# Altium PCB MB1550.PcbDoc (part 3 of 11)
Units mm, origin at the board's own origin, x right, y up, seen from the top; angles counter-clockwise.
Board outline 154.81 x 170.69 mm, 6 copper layers (Top Layer, Signal Layer 1, Signal Layer 2, Signal Layer 3, Signal Layer 4, Bottom Layer), stack 1.49 mm thick; 810 components, 633 nets, 2973 pads, 2150 vias.
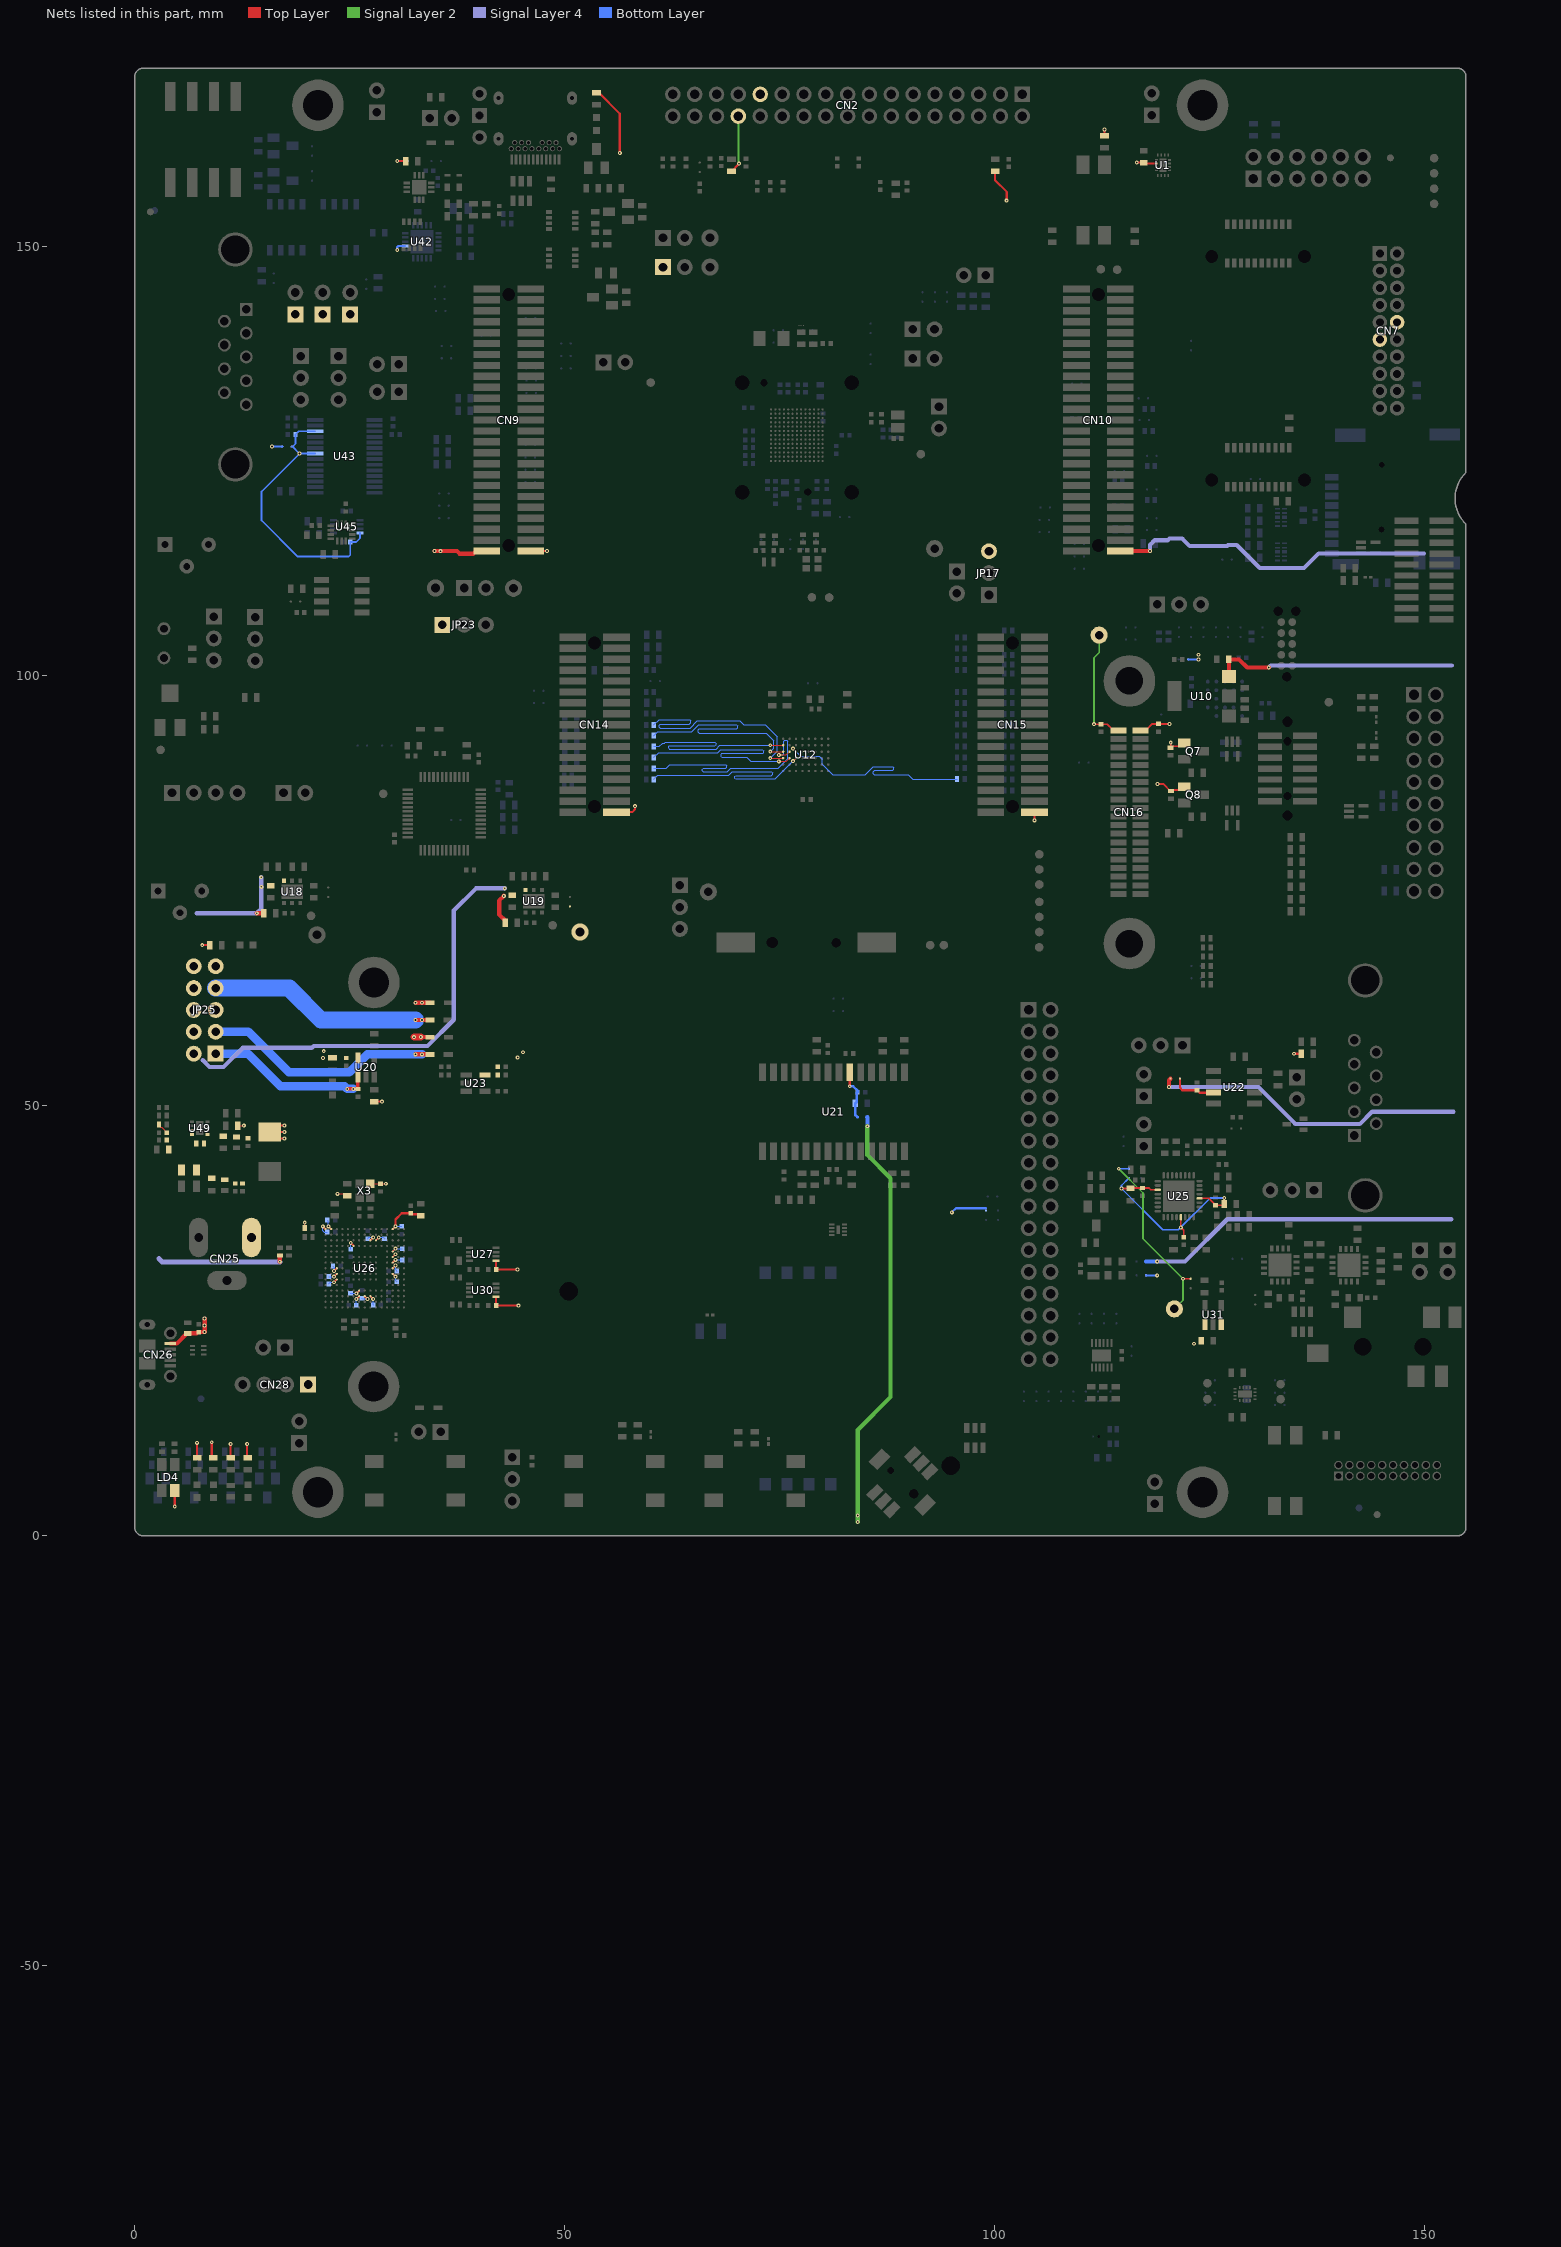
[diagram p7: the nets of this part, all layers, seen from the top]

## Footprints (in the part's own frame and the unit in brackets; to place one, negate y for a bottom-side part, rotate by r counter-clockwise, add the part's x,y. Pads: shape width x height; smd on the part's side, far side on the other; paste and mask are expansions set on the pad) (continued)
PowerFLAT_5x6 [mm] "MCD-02152"
  rect 0.65x1.25 smd mask+0.05: 1(1.905,2.675) 2(0.635,2.675) 3(-0.635,2.675) 4(-1.905,2.675) 5(-1.905,-2.675) 6(-0.635,-2.675) 7(0.635,-2.675) 8(1.905,-2.675)
  Top Layer region: -0.2,-3.3 -0.95,-3.3 -0.95,-2.75 -1.575,-2.75 -1.575,-3.3 -2.3,-3.3 -2.3,-2.3 -2.7,-2.3 -2.7,-1.5 -2.3,-1.5 -2.3,0.15 -2.7,0.15 -2.7,0.975 -2.3,0.975 -2.3,1.15 -0.2,1.15
  Top Layer region: 0.2,-3.3 0.95,-3.3 0.95,-2.75 1.575,-2.75 1.575,-3.3 2.3,-3.3 2.3,-2.3 2.7,-2.3 2.7,-1.5 2.3,-1.5 2.3,0.15 2.7,0.15 2.7,0.975 2.3,0.975 2.3,1.15 0.2,1.15
  silkscreen extent -2.5,-3 2.5,3, body extent -2.6,-3.08 2.6,3.07, height 1
PTC_Panasonic_micro_chip_fuse_0402 [mm] "MCD-02197"
  rect 0.51x0.7 smd mask+0.05: 1(-0.45,0) 2(0.45,0)
  silkscreen extent 0,-0.3 0,0.3, body extent -0.52,-0.3 0.52,0.3, height 0.4
PTH_M1261-3005-N_3P5X6_M3_H14 [mm]
  round 6 hole 3.5 mask+0.05: 1(0,0)
  silkscreen extent -3.25,-3.25 3.25,3.25, body extent -2.5,-2.5 2.5,2.5, height 14
R0402 [mm]
  rect 0.51x0.7 smd mask+0.05: 1(-0.45,0) 2(0.45,0)
  silkscreen extent 0,-0.3 0,0.3, body extent -0.52,-0.3 0.52,0.3, height 0.4
R0603 [mm]
  rect 0.64x1 smd mask+0.05: 1(-0.7,0) 2(0.7,0)
  silkscreen extent -1.05,-0.58 1.05,0.58, body extent -0.9,-0.5 0.9,0.5, height 0.56
R0603_H0P45 [mm]
  rect 0.64x1 smd mask+0.05: 1(-0.7,0) 2(0.7,0)
  silkscreen extent -1.05,-0.58 1.05,0.58, body extent -0.9,-0.5 0.9,0.5, height 0.56
R0805 [mm]
  rect 0.85x1.3 smd mask+0.05: 1(-0.875,0) 2(0.875,0)
  silkscreen extent -0.33,-0.67 0.33,0.67, body extent -1.05,-0.68 1.05,0.68, height 0.65
R0805_H0P5 [mm] "MCD-01537"
  rect 0.85x1.3 smd mask+0.05: 1(-0.875,0) 2(0.875,0)
  silkscreen extent -0.33,-0.67 0.33,0.67, body extent -1.05,-0.68 1.05,0.68, height 0.6
REG_SOT23-5L [mm]
  rect 0.6x1.3 smd mask+0.05: 1(-0.95,-1.1) 2(0,-1.1) 3(0.95,-1.1) 4(0.95,1.1) 5(-0.95,1.1)
  silkscreen extent -1.6,-0.95 1.6,0.97, body extent -1.52,-1.25 1.52,1.25, height 1.1
REG_SOT223-TAB [mm]
  rect 1.5x1.65 smd mask+0.05: 1(-2.3,-3.175) 2(0,-3.175) 3(2.3,-3.175)
  rect 3.5x1.65 smd mask+0.05: 4(0,3.175)
  silkscreen extent -3.35,-2.15 3.35,2.12, body extent -3.35,-3.48 3.35,3.48, height 1.8
SOLDER-BRIDGE_R0603-0R [mil]
  round 10 smd paste-393.7: 1(-19.68,0) 2(23.62,0)
  Top Layer region: -47.24,-19.68 -47.24,19.68 -15.75,19.68 3.94,0 -15.75,-19.68 -47.24,-19.68
  Top Layer region: -5.91,19.68 13.78,0 -5.91,-19.68 47.24,-19.68 47.24,19.68 -5.91,19.68
  silkscreen extent -50,-23 50,23, body extent -36,-20 36,20, height 22
STICKER_BOARD_25X9 [mm] "Sticker to mention board CPN code"
  silkscreen extent -12.5,-4.5 12.5,4.5
STICKER_PRODUCT_25X9 [mm] "Sticker to mention board CPN code"
  silkscreen extent -12.5,-4.5 12.5,4.5
SWI_C&K_SDA02H1SBD_2POS [mm]
  rect 1.5x2.15 smd mask+0.05: 1(-1.27,-4.125) 2(1.27,-4.125) 3(1.27,4.125) 4(-1.27,4.125)
  silkscreen extent -3.55,-3.75 3.55,3.75, body extent -3.53,-4.65 3.53,4.65, height 5.45
SWI_EAO_09-03290-01_EXTENDED_STRAIGHT_BLACK [mm]
  rect 1.7x1.7 hole 0.9 mask+0.05: 1(0,0)
  round 1.7 hole 0.9 mask+0.05: 2(0,-2.54) 3(0,2.54)
  silkscreen extent -1.25,-5 1.25,5, body extent -1.25,-5 1.25,5, height 7.9
SWI_WEALTHMETAL_TD-0341_4P_BLACK [mm]
  rect 1.52x2.16 smd mask+0.05: 1(-2.25,-4.75) 2(-2.25,4.75) 3(2.25,-4.75) 4(2.25,4.75)
  silkscreen extent -3,-3.5 3,3.5, body extent -3,-5.15 3,5.15, height 7.55
SWI_WEALTHMETAL_TD-0341_4P_BLUE [mm]
  rect 1.52x2.16 smd mask+0.05: 1(-2.25,-4.75) 2(-2.25,4.75) 3(2.25,-4.75) 4(2.25,4.75)
  silkscreen extent -3,-3.5 3,3.5, body extent -3,-5.15 3,5.15, height 7.55
SWI_XIEJIA_MT-008A_6P [mm] "MCD-00132"
  rect 1.8x1.1 smd mask+0.05: 1(-3.1,1.4) 2(-3.1,0) 3(-3.1,-1.4) 4(3.1,1.4) 5(3.1,0) 6(3.1,-1.4)
  rect 2.2x1.4 smd mask+0.05: 7(0,3.75) 8(0,-3.75)
  round 0 hole 0.8 unplated paste-10 mask+0.05: NPTH1(0,1.9)
  round 0 hole 1.1 unplated paste-10 mask+0.05: NPTH2(0,-1.9)
  silkscreen extent -3.7,-3.7 3.7,3.7, body extent -3.85,-3.75 3.85,3.75, height 5.2
TP_PTH_1MM_2MM [mm] "MCD-01506"
  round 2 hole 1 mask+0.05: 1(0,0)
  silkscreen extent -1.2,-1.2 1.2,1.2
TP_SMD_1MM [mm]
  round 1 smd paste-10 mask+0.05: 1(0,0)
  silkscreen extent -0.7,-0.7 0.7,0.7
TSB_TOUCH-SENSING-BUTTON_TS-PAD-10_SHIELD-14 [mm]
  round 0.1 smd paste-10 mask+0.05: SHIELD(-0.26,-7.25) SHIELD(0.26,-7.25)
  round 0.12 smd paste-10 mask+0.05: TKEY(0,-7.25)
  Top Layer region: 0,5 -1.913,4.619 -3.536,3.536 -4.619,1.913 -5,0 -5,0 0,0 -5,0 -4.619,-1.913 -3.536,-3.536 -1.913,-4.619 0,-5 0,-5 1.913,-4.619 3.536,-3.536 4.619,-1.913 5,0 5,0 4.619,1.913 3.536,3.536 1.913,4.619 0,5 0,5 0,0
  Top Layer region: -0.21,-5.146 -2.695,-4.388 -4.495,-2.514 -5.15,0 -5.15,0 -4.758,1.971 -3.642,3.642 -1.971,4.758 0,5.15 0,5.15 0,7 -7,7 -7,-7 -0.21,-7
  Top Layer region: 0,5.15 1.971,4.758 3.642,3.642 4.758,1.971 5.15,0 5.15,0 4.495,-2.514 2.695,-4.388 0.21,-5.146 0.21,-5.146 0.21,-7 7,-7 7,7 0,7
  Top Layer lines w0.1: -0.26,-7.25 -0.26,-5.25 ; 0.26,-7.25 0.26,-5.25
  Top Layer lines w0.12: 0,-7.25 0,0
  silkscreen extent -7.12,-7.12 7.12,7.12, body extent -7,-7 7,7, height 4

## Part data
B1: library part MCD-00132, "Joystick, 4 dir, 1 OK", Manufacturer="XIEJIA Electronics", Manufacturer_Part_Number=MT-008A
B2: library part MCD-00001, "Non-Open Push-Button 0.1A 24V", Manufacturer=WEALTHMETAL, Manufacturer_Part_Number=TD0341X-G01-BLA
B3 B4: library part MCD-00002, "Non-Open Push-Button 0.1A 24V", Manufacturer=WEALTHMETAL, Manufacturer_Part_Number=TD0341X-G01-BLU
C1 C33 C39 C66 C72 C76 C77 C80 C85 C87 C88 C89 C96 C99 C100 C101 C102 C109 C145 C148 C149 C180 C181 C188: library part MCD-00010, "Capacitor, MLCC, 1uF, 16V, X5R, 10%, 0603, T=0,8mm", Manufacturer=YAGEO, Manufacturer_Part_Number=CC0603KRX5R7BB105, Package=C0603
C2 C10: library part MCD-00198, "Capacitor, MLCC, 1nF, 16V, X7R, 10%, 0402, T=0.5mm", Manufacturer=YAGEO, Manufacturer_Part_Number=CC0402KRX7R7BB102, Package=C0402
C3 C4 C5 C6 C7 C8 C9 C11 C12 C13 C14 C15 C25 C26 C32 C36 C37 C38 C40 C41 C42 C43 C44 C45 C50 C51 C52 C53 C56 C57 C59 C63 C64 C68 C70 C71 C74 C75 C78 C79 C83 C90 C93 C94 C95 C98 C103 C104 C105 C110 C111 C119 C120 C121 C122 C123 C124 C125 C126 C127 C129 C131 C132 C133 C134 C135 C136 C139 C140 C141 C142 C143 C146 C147 C151 C152 C153 C154 C155 C156 C158 C159 C161 C162 C163 C164 C165 C166 C167 C168 C169 C170 C172 C173 C174 C175 C176 C178 C179: library part MCD-00006, "Capacitor, MLCC, 100nF, 16V, X7R, 10%, 0402, T=0.5mm", Alternate_Manufacturer=MURATA, Alternate_Manufacturer_Part_Number=GCM155R71C104KA55D, Manufacturer=YAGEO, Manufacturer_Part_Number=CC0402KRX7R7BB104, Package=C0402
C16 C62 C97: library part MCD-00011, "Capacitor, MLCC, 10nF, 16V, X7R, 10%, 0402, T=0.5mm", Manufacturer=YAGEO, Manufacturer_Part_Number=CC0402KRX7R7BB103, Package=C0402
C17 C116: library part MCD-01099, "Capacitor,100nF,50V,X7R,10%,0603", Manufacturer=YAGEO, Manufacturer_Part_Number=CC0603KRX7R9BB104, Package=C0603
C18: library part MCD-00015, "Capacitor, MLCC, 10pF, 50V, NPO, 5%, 0402, T=0,5mm", Manufacturer=YAGEO, Manufacturer_Part_Number=CC0402JRNPO9BN100, Package=C0402
C19 C114 C115 C117: library part MCD-00211, "Capacitor, MLCC, 100nF, 16V, X7R, 10%, 0603, T=0,8mm", Manufacturer=YAGEO, Manufacturer_Part_Number=CC0603KRX7R7BB104, Package=C0603
C20: library part MCD-01939, "Capacitor, COG, 39nF,50V, 5%, 1206, T=0.85mm", Manufacturer=MURATA, Manufacturer_Part_Number=GRM3195C1H393JA01D, Package=C1206
C21: library part MCD-02154, "Capacitor, MLCC, 390nF, 10V, X5R, 10%, 0402, T=0,5mm", Alternate_Manufacturer=N\A, Manufacturer=MURATA, Manufacturer_Part_Number=GMD155R61A394KE11J, Package=C0402
C22 C23 C137 C138 C171 C177: library part MCD-01823, "Capacitor,MLCC,2.2uF,6V3,X5R,10%,0402,T=0.5", Manufacturer=MURATA, Manufacturer_Part_Number=GRM155R60J225KE95D, Package=C0402
C24 C107: library part MCD-00205, "Capacitor, MLCC, 100pF, 50V, NPO, 5%, 0402, T=0,5mm", Manufacturer=YAGEO, Manufacturer_Part_Number=CC0402JRNPO9BN101, Package=C0402
C27 C35 C46 C47 C48 C49 C73 C81 C91 C118 C157 C160: library part MCD-00009, "Capacitor, MLCC, 4.7uF, 16V, X5R, 10%, 0603, T=0.8mm", Manufacturer=YAGEO, Manufacturer_Part_Number=CC0603KRX5R7BB475, Package=C0603
C28 C29 C30 C31: library part MCD-00556, "Capacitor, MLCC, 3.9pF, 50V, NPO, +-0.25pF, 0402, T=0,5mm", Manufacturer=YAGEO, Manufacturer_Part_Number=CC0402CRNPO9BN3R9, Package=C0402
C34 C69 C128 C130 C144: library part MCD-01355, "Capacitor, MLCC, 10uF, 4V, X5R, 20%, 0402, T=0,5mm", Manufacturer=MURATA, Manufacturer_Part_Number=GRM155R60G106ME44, Package=C0402
C54 C55 C58 C61 C82: library part MCD-00095, "Capacitor, MLCC, 1uF, 25V, X5R, 10%, 0402, T=0,5mm", Alternate_Manufacturer=MURATA, Alternate_Manufacturer_Part_Number=GRM155R60J105KE19, Manufacturer_Part_Number=GRM155R61E105KA12, Package=C0402
C60: library part MCD-00142, "Capacitor, Tantalum, 220uF, 10V, 10%, TypeC", Manufacturer=AVX, Manufacturer_Part_Number=TAJC227K010R, Package=C2312
C65 C67: library part MCD-00304, "Capacitor, MLCC, 150pF, 50V, COG, 5%, 0603, T=0,8mm", Manufacturer=YAGEO, Manufacturer_Part_Number=CC0603JRNPO9BN151, Package=C0603
C84 C86: library part MCD-00555, "Capacitor, MLCC, 22nF, 10%, 25V, X7R, 0603, T=0,8mm", Manufacturer=YAGEO, Manufacturer_Part_Number=CC0603KRX7R8BB223, Package=C0603
C92: library part MCD-00014, "Capacitor, MLCC, 10uF, 25V, X5R, 10%, 0805, T=0,85mm", Manufacturer=YAGEO, Manufacturer_Part_Number=CC0805KRX5R8BB106, Package=C0805
C106: library part MCD-00012, "Capacitor, MLCC, 2.2uF, 10V, X5R, 10%, 0603, T=0,8mm", Alternate_Manufacturer=KEMET, Alternate_Manufacturer_Part_Number=C0603C225K8PACTU, Manufacturer=YAGEO, Manufacturer_Part_Number=CC0603KRX5R6BB225, Package=C0603
C108: library part MCD-00016, "Capacitor, MLCC, 20pF, 50V, NPO, 5%, 0402, T=0,5mm", Manufacturer=YAGEO, Manufacturer_Part_Number=CC0402JRNPO9BN200, Package=C0402
C112 C113: library part MCD-01579, "Capacitor, MLCC, 330pF, 50V, NPO, +/-5%, 0402, T=0,5mm", Manufacturer=YAGEO, Manufacturer_Part_Number=CC0402JRNPO9BN331, Package=C0402
C150: library part MCD-00100, "Capacitor, MLCC, 22uF, 6V3, X5R, 20%, 0603, T=0,8mm", Manufacturer=MURATA, Manufacturer_Part_Number=GRM188R60J226MEA0J, Package=C0603
C182 C187: library part MCD-00015, "Capacitor, MLCC, 10pF, 50V, NPO, +/-5%, 0402, T=0,5mm", Manufacturer=YAGEO, Manufacturer_Part_Number=CC0402JRNPO9BN100, Package=C0402
C183 C186: library part MCD-02198, "Capacitor, MLCC, 10nF, 50V ,X7R, +/-10%, 0402, T=0.5mm", Alternate_Manufacturer="TAIYO YUDEN", Alternate_Manufacturer_Part_Number=UMF105B7103KVHF, Manufacturer=YAGEO, Manufacturer_Part_Number=CC0402KRX7R9BB103, Package=C0402
C184 C185: library part MCD-02196, "Capacitor, MLCC, 4.7uF, 25V, X5R, +/-10%, 0603, T=0,8mm", Alternate_Manufacturer="TAIYO YUDEN", Alternate_Manufacturer_Part_Number=TMK107BBJ475KA-T, Manufacturer=TDK, Manufacturer_Part_Number=C1608X5R1E475K080AC, Package=C0603
C189: library part MCD-00011, "Capacitor, MLCC, 10nF, 16V, X7R, +/-10%, 0402, T=0.5mm", Manufacturer=YAGEO, Manufacturer_Part_Number=CC0402KRX7R7BB103, Package=C0402
CN1: library part MCD-01108, "USB tyce C certified receptacle for 1.6mm pcb height", Manufacturer="CHANT SINCERE (COXOC)", Manufacturer_Part_Number=317JD24BZTF3K3C3
CN2: library part MCD-00583, "Header, 17x2, 2.54mm, VR, TH, Height 8.89mm/2.92mm, shrouded", Alternate_Manufacturer=WINPIN, Alternate_Manufacturer_Part_Number=BHFS03-34G01BT1, Manufacturer=SAMTEC, Manufacturer_Part_Number=TST-117-01-T-D
CN3: library part MCD-00308, "Socket, 6x2, 2.54mm, TH, RA, Height 8.51mm/7.62mm", Manufacturer=SAMTEC, Manufacturer_Part_Number=SSW-106-02-F-D-RA
CN4: library part MCD-00131, "Socket, 4x2, 2.54mm, RA, SMT, Height 5.72mm", Manufacturer=SAMTEC, Manufacturer_Part_Number=SSM-104-L-DH
CN5 CN11: library part MCD-00675, "Socket High Speed, 10x2, 0.8mm, Center Strip Contacts, VR, SMT, Height 5.33 mm", Manufacturer=SAMTEC, Manufacturer_Part_Number=ERF8-010-05.0-S-DV-TR, Package=ERF8
CN6 CN22: library part MCD-01978, "DB9_Male, RA, TH, height 13.575mm/3.8mm", Manufacturer=TYCO, Manufacturer_Part_Number=2301843-2, Package=TH
CN7: library part MCD-00309, "Socket 10x2, 2.00mm, RA, TH, Height 6.35mm/2.29mm", Alternate_Manufacturer=JIUBABA;CONNECT, Alternate_Manufacturer_Part_Number=FH200020C-12300;CNT-F200-2*10-GD-635/2.3, Manufacturer=SAMTEC, Manufacturer_Part_Number=SQT-110-01-F-D-RA
CN8 CN20: library part MCD-00032, "Header, 2x1, 2,54mm, VR, TH, Height 5.84mm/2.54mm", Manufacturer=SAMTEC, Manufacturer_Part_Number=TSW-102-07-x-S
CN9 CN10: library part MCD-02111, "Header 25x2, 1.27mm, VR, CMS, Height 7.24mm", Alternate_Manufacturer=N/A, Manufacturer=SAMTEC, Manufacturer_Part_Number=FTR-125-03-L-D-LC
CN12: library part MCD-00557, "Header 10x2, 1.27mm, VR, CMS, Height 3.05mm", Alternate_Manufacturer=JIUBABA, Alternate_Manufacturer_Part_Number=P127B-2*10MGF-079-1E7A, Manufacturer=SAMTEC, Manufacturer_Part_Number=FTSH-110-01-L-DV
CN13: library part MCD-00031, "Tag_Connector Header, 10x2, No legs", Manufacturer="TAG-CONNECT LLC", Manufacturer_Part_Number=TC2050-IDC-NL-FP
CN14 CN15: library part MCD-01344, "Header 17x2, 1.27mm, VR, CMS, Height 7.24mm, locking-clip", Manufacturer=SAMTEC, Manufacturer_Part_Number=FTR-117-03-L-D-LC
CN16: library part MCD-00138, "Socket, 20x2, 1.0mm, VR, SMT, Height 2.26mm. Symbol & Footprint dedicated to MB1183 & MB1379 camera modules (not in line with Samtec datasheet)", Manufacturer=SAMTEC, Manufacturer_Part_Number=CLM-120-02-L-D
CN17: library part MCD-01058, "Header, 2.54mm, 10x2, VR, TH, Height 9.1mm/3,1mm", Alternate_Manufacturer=CVILUX, Alternate_Manufacturer_Part_Number=CH87-20-2-V-1-00, Manufacturer=SAMTEC, Manufacturer_Part_Number=TST-110-01-G-D
CN18: library part MCD-01226, "Header 5x2, 1.27mm, Dual row, Straight, Surface mount, vertical male connector. 3.05mm lead. Mates with FFSD connector. Footprint compatible with FTSH-107-01-L-DV,-K,-A,-P,-ES (STDC14 MEDIUM)", Alternate_Manufacturer=JIUBABA, Alternate_Manufacturer_Part_Number=P127B-2x05MGF-079-1A, Manufacturer=SAMTEC, Manufacturer_Part_Number=FTSH-105-01-L-DV-K
CN19 CN28: library part MCD-00029, "Header, 4x1, 2,54mm, VR, TH, Height 5.84mm/2.54mm", Manufacturer=SAMTEC, Manufacturer_Part_Number=TSW-104-07-x-S
CN21: library part MCD-00558, "Battery Coin Cell holder, CR1220_12mm, Height 4.25mm", Manufacturer=HARWIN, Manufacturer_Part_Number=S8411-45R
CN23: library part MCD-01342, "Socket, 17x2, 2.54mm, VR, TH, Height 8.51mm/2.64mm, Low insertion force for TFT LCD MB989", Manufacturer=SAMTEC, Manufacturer_Part_Number=SSW-117-21-x-D
CN24: library part MCD-00111, "Header, 3x1, 2,54mm, VR, TH, Height 5.84mm/2.54mm", Manufacturer=SAMTEC, Manufacturer_Part_Number=TSW-103-07-F-S
CN25: library part MCD-00173, "DC-Power-Jack, 2.5mm, 5A, RA, TH", Manufacturer=CLIFF, Manufacturer_Part_Number=DC10B
CN26: library part MCD-00028, "USB-MICRO-B, 0.65mm, RA, SMT, Bottom Mount,", Manufacturer=MOLEX, Manufacturer_Part_Number=1050170001
CN27: library part MCD-00263, "Connector Jack Socket Stereo 3.5mm, 4 pins, RA, SMT, Black", Manufacturer=QIAOD, Manufacturer_Part_Number=PJ3028B-3_4P
CN29: library part MCD-00147, "Socket, 10x2, 1.27mm, VR, TH, Height 4.30mm/2.40mm", Manufacturer=FCI, Manufacturer_Part_Number=20021311-00020T4LF
CN30: library part MCD-00023, "MicroSD Card Conn, Reversed-Type, Mnt Push-Push, Positionning holes", Manufacturer=YAMAICHI, Manufacturer_Part_Number=PJS008-2003-1
CN31: library part MCD-01175, "IC Card Socket 8 pin, SMT Open for Smartcard", Manufacturer="GUANG LIAN WEI", Manufacturer_Part_Number=2480-208-503-100-RC
D1 D3 D9: library part MCD-00034, "BAT60JFILM", Manufacturer=STMICROELECTRONICS
D2: library part MCD-01677, "Small signal Schottky diodes", Manufacturer=STMICROELECTRONICS, Manufacturer_Part_Number=BAT54KFILM, Package=SOD-523
D4 D5 D6 D7: library part MCD-00034, Manufacturer=STMICROELECTRONICS
D8: library part MCD-01229, "3 line IPAD, EMI filter for SIM card applications", Manufacturer=STMICROELECTRONICS
F1: library part MCD-02197, "Micro Chip Fuse, Fast Acting, 2A, 53mOhm, 32V Rated Voltage", Alternate_Manufacturer=N/A, Manufacturer=PANASONIC, Manufacturer_Part_Number=ERBRD2R00X, Package=0402
H1 H2 H3 H4 H5 H6: library part MCD-00035, "POSITION HOLE C6D3R5"
HW100: library part MCD-00235, "Sticker Board 25x9 mm", Alternate_Manufacturer=N/A
HW101: library part MCD-00547, "Sticker product 25x9 mm", Alternate_Manufacturer=N/A
JP1 JP2 JP3 JP7 JP9 JP12 JP13 JP15 JP27 JP28 JP29 JP30 JP31 JP32 JP33 JP34 JP36: library part MCD-00045, "Header, 2x1, 2,54mm, VR, TH, Height 5.84mm/2.54mm", Manufacturer=SAMTEC, Manufacturer_Part_Number=TSW-102-07-x-S
JP4 JP5 JP6 JP8 JP14 JP16 JP18 JP19: library part MCD-00683, "Header, 2x1, 2,54mm, VR, TH, Height 5.84mm/2.54mm - Shunt Fitted by default", Manufacturer=SAMTEC, Manufacturer_Part_Number=TSW-102-07-x-S
JP10 JP11 JP17 JP20 JP21 JP23 JP24 JP26 JP35: library part MCD-00684, "Header, 3x1, 2,54mm, VR, TH, Height 5.84mm/2.54mm - Shunt Fitted 1-2 by default", Manufacturer=SAMTEC, Manufacturer_Part_Number=TSW-103-07-F-S
JP22: library part MCD-00685, "Header, 3x1, 2,54mm, VR, TH, Height 5.84mm/2.54mm - Shunt Fitted 2-3 by default", Manufacturer=SAMTEC, Manufacturer_Part_Number=TSW-103-07-F-S
JP25: library part MCD-01203, "Header, 5x2, 2,54mm, VR, TH, Height 5.84mm/2.54mm - Shunt Fitted 1-2", Manufacturer=SAMTEC, Manufacturer_Part_Number=TSW-105-07-x-D
L1: library part MCD-01060, "Inductor, 2.2uH, 20%, Isat 0.7A, DCR 0.156Ohm, 0805", Manufacturer=MURATA, Manufacturer_Part_Number=LQM21PN2R2MGH, Package=L0805
L3 L4: library part MCD-00047, "SMD Chip ferrite bead, 600R@100MHz +/-25%, 350mA, 500mohm DC, 0603, T=0.8mm", Manufacturer=TAI-TECH, Manufacturer_Part_Number=FCM1608KF-601T03
LD1 LD2 LD5: library part MCD-00588, "LED Green, 0603 SMD, Forward Voltage Typ=2V, Max=2.5V", Alternate_Manufacturer="VISHAY SEMICONDUCTOR OPTO DIVISION", Alternate_Manufacturer_Part_Number=VLMTG1300-GS08, Manufacturer="OSRAM OPTO SEMICONDUCTORS", Manufacturer_Part_Number="LG Q396-PS-35", Package="LED 0603"
LD3 LD6: library part MCD-00587, "LED Red, 0603 SMD, 2V Forward Voltage", Alternate_Manufacturer="OSRAM OPTO SEMICONDUCTORS", Alternate_Manufacturer_Part_Number="LS Q976-NR-1", Manufacturer=VISHAY, Manufacturer_Part_Number=VLMS1300-GS08, Package="LED 0603"
LD4: library part MCD-00051, "LED Bicolor", Alternate_Manufacturer=EVERLUCK, Alternate_Manufacturer_Part_Number=LE-RGW35280, Manufacturer="AVAGO TECHNOLOGIES", Manufacturer_Part_Number=HSMF-A201-A00J1
LD7: library part MCD-01131, "LED Blue, 0603 SMD, Forward Voltage Min=2,8V, Max=3,1V", Manufacturer=EVERLIGHT, Manufacturer_Part_Number=19-217-BHC-ZL1M2RY-3T, Package=0603
LD8: library part MCD-01061, "LED Yellow, 0603 SMD, Forward Voltage min=1.7V, Typ=2V, Max=2.3V", Manufacturer="OSRAM OPTO SEMICONDUCTORS", Manufacturer_Part_Number="LY Q396-P1Q2-36"
Q1 Q9 Q14 Q15 Q16 Q17: library part MCD-00073, "NPN Bipolar Transistor", Manufacturer=NXP, Manufacturer_Part_Number=BSR14
Q2 Q6 Q10 Q11: library part MCD-01164, "N-channel Digital FET", Manufacturer=FAIRCHILD, Manufacturer_Part_Number=FDV303N, Package=SOT-23
Q3 Q5: library part MCD-01126, "Power Mosfet, P-channel,VDS -30V,RDS 12mohm typ,ID -9A", Manufacturer=STMICROELECTRONICS, Package="PowerFLAT 3.3x3.3"
Q4: library part MCD-01810, "N-channel 30 V, 6 mΩ typ, 11 A STripFET™ H6, Power MOSFET in a PowerFLAT™ 3.3x3.3 package", Manufacturer=STMICROELECTRONICS, Manufacturer_Part_Number=STL11N3LLH6, Package="PowerFLAT 3.3x3.3"
Q7 Q8: library part MCD-02156, "MOSFET, N-Channel , Vds: 25V, Id: 0,22A, Vgs(th): 1.06V, Vgs(max): +/-8V, Rdson:5ohm@Vgs=2.7V, Qg=0,49nC", Alternate_Manufacturer=N/A, Manufacturer="ON SEMICONDUCTOR", Manufacturer_Part_Number=FDV301N, Package=SOT23-3
Q12 Q13: library part MCD-02152, "Dual N-channel 30 V, 0.016 Ω typ., 40 A, STripFET™ H5 Power MOSFET", Alternate_Manufacturer=N/A, Manufacturer=STMICROELECTRONICS, Package="PowerFLAT 5x6"
R1 R130: library part MCD-00442, "Resistor,270R,0603,1%,1/10W", Manufacturer=YAGEO, Manufacturer_Part_Number=RC0603FR-07270RL, Package=R0603
R2 R3 R4 R13 R15 R20 R21 R23 R24 R32 R36 R37 R45 R52 R64 R65 R73 R76 R79 R85 R89 R90 R92 R94 R95 R96 R102 R119 R127 R136 R137 R142 R174 R195 R201 R230 R231 R232 R233 R235 R236 R248: library part MCD-00220, "Resistor,10K,0603,1%,1/10W", Manufacturer=YAGEO, Manufacturer_Part_Number=RC0603FR-0710KL, Package=R0603
R5 R6 R108: library part MCD-00352, "Resistor,3K3,0603,1%,1/10W", Manufacturer=YAGEO, Manufacturer_Part_Number=RC0603FR-073K3L, Package=R0603
R7 R16 R17 R29 R74 R75 R82 R84 R86 R87 R88 R110 R118 R122 R124 R167 R170 R241 R242 R243 R244: library part MCD-00223, "Resistor,100K,0603,1%,1/10W", Manufacturer=YAGEO, Manufacturer_Part_Number=RC0603FR-07100KL, Package=R0603
R8 R104 R165 R166 R169 R172 R173 R237 R238 R239 R240: library part MCD-00222, "Resistor,47K,0603,1%,1/10W", Manufacturer=YAGEO, Manufacturer_Part_Number=RC0603FR-0747KL, Package=R0603
R9 R93: library part MCD-00430, "Resistor,22K,0603,1%,1/10W", Manufacturer=YAGEO, Manufacturer_Part_Number=RC0603FR-0722KL, Package=R0603
R10 R147 R149: library part MCD-00218, "Resistor,2K7,0603,1%,1/10W", Manufacturer=YAGEO, Manufacturer_Part_Number=RC0603FR-072K7L, Package=R0603
R11: library part MCD-00458, "Resistor,330K,0603,1%,1/10W", Manufacturer=YAGEO, Manufacturer_Part_Number=RC0603FR-07330KL, Package=R0603
R12: library part MCD-01171, "Resistor,49K9,0603,1%", Manufacturer=YAGEO, Manufacturer_Part_Number=RC0603FR-0749K9L, Package=R0603
R14 R112: library part MCD-00224, "Resistor,100R,0603,1%,1/10W", Manufacturer=YAGEO, Manufacturer_Part_Number=RC0603FR-07100RL, Package=R0603
R18: library part MCD-01189, "Resistor,21K,0603,1%,1/10W", Manufacturer=YAGEO, Manufacturer_Part_Number=RC0603FR-0721KL, Package=R0603
R19: library part MCD-01578, "Resistor, 1K, 0805, 1%, 1/8W", Manufacturer=YAGEO, Manufacturer_Part_Number=RC0805FR-071KL, Package=R0805
R22 R39 R41 R43 R44 R47 R55 R61 R63 R67 R80 R91 R105 R111 R251: library part MCD-00070, "Resistor,1K,0603,1%,1/10W", Manufacturer=YAGEO, Manufacturer_Part_Number=RC0603FR-071KL, Package=R0603
R25 R26 R27 R28 R103 R113 R139 R140 R145 R148 R150 R151 R152 R155 R158 R159 R160 R162 R163 R164 R175 R177 R178 R179 R180 R182 R183 R185 R186 R188 R189 R190 R191 R192 R193 R196 R197 R198 R199 R200 R203 R204 R205 R207 R208 R209 R213 R214 R215 R217 R218 R219 R221 R222 R223 R224 R225 R226 R227 R228 R229 R250: library part MCD-00052, "Resistor,0R,0402,5%,1/16W", Manufacturer=YAGEO, Manufacturer_Part_Number=RC0402JR-070RL, Package=R0402
R30 R31 R49 R51 R77 R78 R120 R121 R134 R135 R143 R144 R146 R153 R154 R157 R161 R168 R171 R176 R181 R184 R187 R194 R202 R206 R210 R211 R212 R216 R220: library part MCD-00056, "Resistor,0R,0603,5%,1/10W", Manufacturer=YAGEO, Manufacturer_Part_Number=RC0603JR-070RL, Package=R0603
R33: library part MCD-01158, "GL55 series  photoconductive cell", Manufacturer="SHENZHEN SENBAN OPTICAL & ELECTRONIC CO. LTD", Manufacturer_Part_Number=GL5528
R34: library part MCD-00530, "Resistor,8K2,0603,1%,1/10W", Manufacturer=YAGEO, Manufacturer_Part_Number=RC0603FR-078K2L, Package=R0603
R35 R81: library part MCD-00338, "Resistor,120R,0603,1%,1/10W", Manufacturer=YAGEO, Manufacturer_Part_Number=RC0603FR-07120RL, Package=R0603
R38: library part MCD-00347, "Resistor,220K,0603,1%,1/10W", Manufacturer=YAGEO, Manufacturer_Part_Number=RC0603FR-07220KL, Package=R0603
R40 R46 R53 R54 R58 R62: library part MCD-00066, "Resistor,22R,0603,1%,1/10W", Manufacturer=YAGEO, Manufacturer_Part_Number=RC0603FR-0722RL, Package=R0603
R42: library part MCD-00394, "Resistor,150,0603,1%,1/10W", Manufacturer=YAGEO, Manufacturer_Part_Number=RC0603FR-07150RL, Package=R0603
R48 R50 R100 R101 R107: library part MCD-00065, "Resistor,4K7,0402,1%,1/16W", Alternate_Manufacturer=YAGEO, Alternate_Manufacturer_Part_Number=RT0402FRE074K7L, Manufacturer_Part_Number=RC0402FR-074K7L, Package=R0402
R56 R126: library part MCD-00422, "Resistor,20K,0603,1%,1/10W", Manufacturer=YAGEO, Manufacturer_Part_Number=RC0603FR-0720KL, Package=R0603
R57: library part MCD-01155, "Resistor,10K2,0603,1%,1/10W", Manufacturer=YAGEO, Manufacturer_Part_Number=RC0603FR-0710K2L, Package=R0603
R59: library part MCD-01149, "Resistor,20K5,0603,1%,1/10W", Manufacturer=YAGEO, Manufacturer_Part_Number=RC0603FR-0720K5L, Package=R0603
R60: library part MCD-00244, "Resistor,11K8,0603,1%,1/10W", Manufacturer=YAGEO, Manufacturer_Part_Number=RC0603FR-0711K8L, Package=R0603
R66 R68 R69 R70 R71 R72: library part MCD-00481, "Resistor,47R,0402,1%,1/16W", Manufacturer=YAGEO, Manufacturer_Part_Number=RC0402FR-0747RL, Package=R0402
R83: library part MCD-00349, "Resistor,2K2,0603,1%,1/10W", Manufacturer=YAGEO, Manufacturer_Part_Number=RC0603FR-072K2L, Package=R0603
R97 R114 R116 R117: library part MCD-00067, "Resistor,100R,0402,1%,1/16W", Manufacturer=YAGEO, Manufacturer_Part_Number=RC0402FR-07100RL, Package=R0402
R98 R99: library part MCD-00564, "Resistor,49R9,0603,1%,1/10W", Manufacturer=YAGEO, Manufacturer_Part_Number=RC0603FR-0749R9L, Package=R0603
R106: library part MCD-00055, "Resistor,2K7,0402,1%,1/16W", Manufacturer=YAGEO, Manufacturer_Part_Number=RC0402FR-072K7L, Package=R0402
R109: library part MCD-00680, "Resistor, SMD PTS 100ohm @ 0°C Flat Chip Temperature Sensor", Manufacturer=VISHAY, Manufacturer_Part_Number=PTS060301B100RP100, Package=R0603
R115: library part MCD-00185, "Resistor,3K,0402,1%,1/16W", Manufacturer=YAGEO, Manufacturer_Part_Number=RC0402FR-073KL, Package=R0402
R123 R125: library part MCD-00418, "Resistor,200R,0603,1%,1/10W", Manufacturer=YAGEO, Manufacturer_Part_Number=RC0603FR-07200RL, Package=R0603
R128 R129: library part MCD-00062, "Resistor,330R,0402,1%,1/16W", Manufacturer=YAGEO, Manufacturer_Part_Number=RC0402FR-07330RL, Package=R0402
R131 R132: library part MCD-00462, "Resistor,360R,0603,1%,1/10W", Manufacturer=YAGEO, Manufacturer_Part_Number=RC0603FR-07360RL, Package=R0603
R133: library part MCD-00354, "Resistor,470R,0603,1%,1/10W", Manufacturer=YAGEO, Manufacturer_Part_Number=RC0603FR-07470RL, Package=R0603
R138: library part MCD-02151, "Current Detection Resistor, 0R047, 0805, 1%, 1/4W", Alternate_Manufacturer=N/A, Manufacturer=YAGEO, Manufacturer_Part_Number=RL0805FR-7W0R047L, Package=R0805
R141: library part MCD-00434, "Resistor,2K4,0603,1%,1/10W", Manufacturer=YAGEO, Manufacturer_Part_Number=RC0603FR-072K4L, Package=R0603
R156: library part MCD-00528, "Resistor,820R,0603,1%,1/10W", Manufacturer=YAGEO, Manufacturer_Part_Number=RC0603FR-07820RL, Package=R0603
R234: library part MCD-00225, "Resistor,510R,0603,1%,1/10W", Manufacturer=YAGEO, Manufacturer_Part_Number=RC0603FR-07510RL, Package=R0603
R245 R246: library part MCD-00219, "Resistor,4K7,0603,1%,1/10W", Manufacturer=YAGEO, Manufacturer_Part_Number=RC0603FR-074K7L, Package=R0603
R247 R252: library part MCD-00179, "Resistor,0R,0805,5%?1/8W", Manufacturer=YAGEO, Manufacturer_Part_Number=RC0805JR-070RL, Package=R0805
R249: library part MCD-00182, "Resistor,1M,0402,1%,1/16W", Manufacturer=YAGEO, Manufacturer_Part_Number=RC0402FR-071ML, Package=R0402
RV1: library part MCD-02051, "Trimmer, 10K, 3386, +/-10%, 1/2W, T=4.83mm", Alternate_Manufacturer=N/A, Manufacturer=BOURNS, Manufacturer_Part_Number=3386P-1-103TLF, Package=3386P
RV2: library part MCD-01169, "4mm Square Trimming Potentiometer 10K OHM 0.25W PC PIN", Manufacturer=BOURNS, Manufacturer_Part_Number=3314J-1-103
RV3: library part MCD-01156, "Trimmer, 50K, 3386P, +/-10%, 1/2W, T=10.41mm", Alternate_Manufacturer=N/A, Manufacturer=BOURNS, Manufacturer_Part_Number=3386P-1-503TLF, Package=3386P
SB1 SB2 SB3 SB4 SB5 SB6 SB7 SB8 SB9 SB10 SB11 SB12 SB13 SB14 SB15 SB16 SB17 SB18 SB19 SB20 SB21 SB22 SB23 SB24 SB25 SB26 SB27 SB28 SB29 SB30 SB31 SB32 SB33 SB34 SB35 SB36 SB37 SB38 SB39 SB40 SB41 SB42 SB43 SB44 SB45 SB46 SB47 SB48 SB49 SB50 SB51 SB52 SB53 SB54 SB55 SB56 SB57 SB58 SB59 SB60 SB61 SB62 SB63 SB65 SB66 SB67 SB68 SB69 SB70 SB71 SB72 SB73 SB74 SB75 SB76 SB77 SB78 SB79 SB80 SB81 SB82 SB83 SB84 SB85 SB86 SB87 SB88 SB89 SB90 SB91 SB92 SB93 SB94 SB95 SB96 SB97 SB98 SB99 SB100 SB101 SB102 SB103 SB104 SB105 SB106 SB107 SB108 SB109 SB110 SB111 SB112 SB113 SB114 SB115 SB116 SB117 SB118 SB119 SB120 SB121 SB122 SB123 SB124 SB125 SB126 SB127 SB128 SB129 SB130 SB131 SB132 SB133 SB134 SB135 SB136 SB137 SB138 SB139 SB140 SB141 SB142 SB143 SB144 SB145 SB146 SB147: library part MCD-00071, "Solder Bridge ON"
SB64: library part MCD-00071, "Solder Bridge ON", Manufacturer=YAGEO, Manufacturer_Part_Number=RC0603JR-070RL, Package=SB0603
SW1: library part MCD-00566, "Mechanical Slide Switches 1K2 BLK ACT GOLD STRT MNT", Manufacturer=EAO, Manufacturer_Part_Number=09.03290.01
SW2 SW3: library part MCD-00658, "Dip Switch ,2Position ,Surface Mount Slide (Standard) ,2.54 pitch,25mA 24VDC", Manufacturer=C&K, Manufacturer_Part_Number=SDA02H1SBD, Package=DIP
TP1 TP2 TP3 TP4 TP7 TP8 TP9 TP10 TP14 TP15 TP17 TP18 TP19 TP20 TP21 TP22 TP24 TP25 TP26 TP27 TP30 TP31 TP32 TP33 TP35 TP36 TP37 TP38: library part MCD-00074, "Test Point 1mm", Manufacturer=n/a
TP5 TP6 TP11 TP12 TP13 TP16 TP23 TP28 TP29 TP34: library part MCD-01506, "Test Point trought hole 1mm/2mm", Manufacturer=n/a
TS1: library part MCD-01194, "-Touch Sensing button: diameter 10mm min,  active shield diameter 12mm min", Manufacturer=n/a, Manufacturer_Part_Number=Touch_sensing_Button
U1 U37: library part MCD-00317, "Low voltage high bandwidth quad SPDT switch", Manufacturer=STMICROELECTRONICS
U2: library part MCD-01809, "USB Type-C Port Protection for USB Power Delivery, PPS compliant", Manufacturer=STMICROELECTRONICS, Manufacturer_Part_Number=TCPP01-M12, Package=QFN-12L
U3: library part MCD-00163, "Very low capacitance ESD protection", Manufacturer=STMICROELECTRONICS
U4: library part MCD-01207, "High power Transient voltage suppressor:25V/35A EOS and ESD transients protection.", Manufacturer=STMICROELECTRONICS, Manufacturer_Part_Number=ESDA25P35-1U1M, Package=QFN1610
U5: library part MCD-01902, "MCU, STM32U575AII6Q,Low Power BGA169 7x7, pitch0.5, no AES, Q for Int SMPS, with socket footprint IRONWOOD CS1627113MF MCD-01903", Alternate_Manufacturer=N/A, Manufacturer=STMICROELECTRONICS, Manufacturer_HQ_COO=EU, Manufacturer_Part_Number="STM32U575AII6Q (CS1627113MF)", Package=BGA169
U6: library part MCD-01499, "iNEMO inertial module: always-on 3D accelerometer and 3D gyroscope", Manufacturer=STMICROELECTRONICS, Package="LGA-14L 2.5x3"
U7 U16: library part MCD-00136, "Dual Transil array for ESD protection", Manufacturer=STMICROELECTRONICS, Manufacturer_Part_Number=ESDALC6V1W5
U8: library part MCD-00293, "I2C memory", Manufacturer=STMICROELECTRONICS, Manufacturer_Part_Number=M24128-DFMN6TP
U9 U11 U13 U33 U39 U40 U41: library part MCD-00170, "ESD protection 6V1", Manufacturer=STMICROELECTRONICS, Manufacturer_Part_Number=ESDALC6V1-1U2
U10: library part MCD-00721, "LDO Voltage Regulator, Adjustable, 15V in, 1.1V drop, 1.25V to 15V/0.8A out, SOT-223-3", Manufacturer=STMICROELECTRONICS, Manufacturer_Part_Number=LD1117STR, Package=SOT223
U12: library part MCD-00560, "SRAM 16Mb 10ns 1Mx16 Async SRAM 3.3v", Manufacturer=ISSI, Manufacturer_Part_Number=IS61WV102416BLL-10MLI
U14 U17: library part MCD-00136, "Dual Transil array for ESD protection", Manufacturer=STMICROELECTRONICS
U15: library part MCD-00135, "Ultra-low-power 32-bit MCU ARM", Manufacturer=STMICROELECTRONICS, Manufacturer_Part_Number=STM32L152CCT6
U18 U19: library part MCD-00581, "LDO Linear Voltage Regulator IC Positive Adjustable 1 Output Adjustable 1.3A 6-DFN (3x3)", Manufacturer=STMICROELECTRONICS, Manufacturer_Part_Number=ST1L05BPUR, Package="DFN6 (3x3)"
U20: library part MCD-02309, "Power Switch, 5V, 0.85A, RDSon 130mOhm max, with active High enable pin and resistor discharge", Alternate_Manufacturer=N/A, Manufacturer="TEXAS INSTRUMENTS", Manufacturer_Part_Number=TPS2051CDBVT, Package=SOT23_5p
U21: library part MCD-01162, "Smartcard interfaces", Manufacturer=STMICROELECTRONICS, Manufacturer_Part_Number=ST8024LACDR
U22: library part MCD-00129, "High-Speed CAN Flexible Data Rate Transceiver", Manufacturer=MICROCHIP, Manufacturer_Part_Number=MCP2562FDT-H/SN
U23: library part MCD-00086, "Ultra low drop-low noise BiCMOS voltage, regulators low ESR capacitors compatible", Manufacturer=STMICROELECTRONICS
U24: library part MCD-01358, "Automotive dual-line Transil, transient voltage suppressor (TVS) for CAN bus 36V. Compliant with interfaces in automotive: CAN-FD, LIN, FlexRay, MOST, SENT, USB", Manufacturer=STMICROELECTRONICS, Manufacturer_Part_Number=ESDCAN05-2BWY, Package=SOT323-3L
U25: library part MCD-00265, "Low-Power, Stereo Codec with Headphone Amp", Manufacturer="CIRRUS LOGIC", Manufacturer_Part_Number=CS42L51-CNZ
U26: library part MCD-00596, "STM32F723IEK  (STM32F7) BGA176", Manufacturer=STMICROELECTRONICS, Manufacturer_Part_Number=STM32F723IEK6
U27 U30: library part MCD-00264, "Dual bit dual supply bus transceiver", Manufacturer="TEXAS INSTRUMENTS"
U28 U29: library part MCD-00681, "Smart sensor II dual-channel 1-bit, 4 MHz, second-order sigmadelta modulator with embedded PGLNA", Manufacturer=STMICROELECTRONICS, Manufacturer_Part_Number=STPMS2L-PUR, Package="QFN16 (4x4 mm)"
U31: library part MCD-00078, "Ultra low drop-low noise BiCMOS voltage, regulators low ESR capacitors compatible", Manufacturer=STMICROELECTRONICS, Manufacturer_Part_Number=LD3985M18R
U32: library part MCD-00247, "Quad Bidir ESD protection", Manufacturer=STMICROELECTRONICS, Manufacturer_Part_Number=ESDA6V1BC6
U34: library part MCD-01026, "High power transient voltage suppressor", Manufacturer=STMICROELECTRONICS, Manufacturer_Part_Number=ESDA7P120-1U1M, Package=QFN1610
U35: library part MCD-01952, "Multitouch 4-wire Resistive Touchscreen Controller with 15kV ESD Protection", Manufacturer=SEMTECH, Manufacturer_Part_Number=SX8651IWLTRT, Package="DFN 3x3"
U36: library part MCD-00649, "Common mode filter with ESD protection for USB 2.0 interface", Manufacturer=STMICROELECTRONICS, Manufacturer_Part_Number=ECMF02-2AMX6
U38: library part MCD-01066, "5 unidirectional Transil diodes ESD protection", Manufacturer=STMICROELECTRONICS, Manufacturer_Part_Number=ESDA6V1-5SC6, Package=SOT23-6L
U42: library part MCD-02130, "USB Type-C Port Protection for USB DRP Power Delivery, PPS compliant", Alternate_Manufacturer=N/A, Manufacturer=STMICROELECTRONICS, Package=QFN-20L
U43: library part MCD-00152, "RS-232 transceiver with auto-power-down", Manufacturer=STMICROELECTRONICS, Manufacturer_Part_Number=ST3241EBPR
U44 U46: library part MCD-00667, "4-line ESD protection for high speed lines", Manufacturer=STMICROELECTRONICS, Manufacturer_Part_Number=HSP051-4M10, Package=uQFN-10L
U45: library part MCD-00264, "Dual bit dual supply bus transceiver", Manufacturer="TEXAS INSTRUMENTS", Manufacturer_Part_Number=SN74LVC2T45DCUT
U47: library part MCD-00246, "Memory,Octo-SPI-NOR,512Mb,2048x16,133MHz,3V,DTR,BGA24, CMOS MXSMIO", Manufacturer=MACRONIX, Package=BGA24
U48: library part MCD-02122, "MEMS sensors , omnidirectionnal digital microphone", Alternate_Manufacturer=N/A, Manufacturer=STMICROELECTRONICS, Manufacturer_HQ_COO=EU, Manufacturer_Part_Number=MP23DB01HPTR, Package="RHLGA 5"
U49: library part MCD-02194, "eFuse with Fast Overvoltage Protection 2.7V to 18V 4A 34mOhm 8-Pin WSON", Alternate_Manufacturer="TEXAS INSTRUMENTS", Alternate_Manufacturer_Part_Number=TPS259533DSGT, Manufacturer_Part_Number=TPS259533DSGR, Package=WSON8
U50: library part MCD-02195, "Diode, High power transient voltage suppressor, 13V breakdown", Alternate_Manufacturer=N/A, Manufacturer=STMICROELECTRONICS, Manufacturer_HQ_COO=EU, Manufacturer_Part_Number=ESDA13P70-1U1M, Package=QFN1610
U51: library part MCD-00251, "High power transient voltage suppressor, 7V breakdown", Manufacturer=STMICROELECTRONICS, Manufacturer_HQ_COO=EU, Manufacturer_Part_Number=ESDA7P60-1U1M
X1: library part MCD-01476, "Crystal 16 MHz, 8pF, -+20 PPM, R=200Ω, SMD", Manufacturer=NDK, Manufacturer_Part_Number="NX2016SA 16 MHz EXS00A-CS07826", Package=NX2016SA
X2: library part MCD-02291, "Crystal 32.768kHz, 9pF, -+20ppm, 70Kohm max, SMD", Alternate_Manufacturer=N/A, Manufacturer=NDK, Manufacturer_Part_Number="NX1610SE 32.768KHz EXS00A-MU01499", Package=NX1610SE
X3: library part MCD-00597, "Oscillator 25Mhz, +-50ppm, Vcc:3.3V typ, square wave: [0.1Vcc;0.9Vcc], Enable pin, SMD", Alternate_Manufacturer=NDK, Alternate_Manufacturer_Part_Number="NZ2520SB 25MHz END4869B", Manufacturer_Part_Number="NZ2520SH 25MHz END4869C"

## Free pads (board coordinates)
  round 0.508 on Mech16: 1(46.503,-75.548) 1(95.351,-75.548)

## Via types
v1: diameter 0.45, hole 0.2, Top Layer to Bottom Layer, tented both sides, 1777 vias
v2: diameter 0.25, hole 0.1, Top Layer to Signal Layer 1, tented top, 344 vias
v3: diameter 0.25, hole 0.1, Signal Layer 1 to Signal Layer 2, 29 vias

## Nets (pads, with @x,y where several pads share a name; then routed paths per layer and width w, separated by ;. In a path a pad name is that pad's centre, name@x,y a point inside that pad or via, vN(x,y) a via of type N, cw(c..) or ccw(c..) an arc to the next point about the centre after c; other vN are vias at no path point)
1V8: SB7.2 SB121.1 TP34.1 | length 21.9
  Top Layer w0.2: v1(121.9,29.9) SB7.2@122.8,29.9
  Signal Layer 2 w0.2: v1(114.425,42.7) 117.248,39.877 117.248,34.552 v1(121.9,29.9) 121.9,27.4 TP34.1@120.9,26.4
  Bottom Layer w0.2: v1(114.425,42.7) SB121.1@115.6,42.7
1V8_CODEC: C77.2 C78.1 C79.1 C80.2 C90.1 SB121.2 U25.5 U25.12 U25.27 | length 27.8
  Top Layer w0.2: v1(114.75,40.4) C77.2@115.8,40.4 115.85,40.45 C78.1@117.2,40.45 117.95,40.45 118.15,40.25 U25.27@118.975,40.25 ; U25.5@121.65,37.075 v1(121.65,35.875) 122,35.525 C90.1@122,34.75 ; U25.12@123.825,39.25 124.9,39.25 C79.1@125.7,38.45 126.55,38.45 C80.2@126.7,38.6 v1(126.7,39.3)
  Bottom Layer w0.2: SB121.2@115.6,41.6 114.75,40.75 v1(114.75,40.4) 119.554,35.596 121.371,35.596 v1(121.65,35.875) 125.075,39.3 v1(126.7,39.3)
2V8: C37.2 C38.2 CN16.39 CN16.40 Q7.1 Q8.1 R48.2 R50.2 SB104.2 TP16.1 | length 24.7
  Top Layer w0.2: v1(111.55,94.4) C38.2@112.35,94.4 113.075,94.4 113.82,93.655 CN16.40@114.4,93.655 ; CN16.39@116.95,93.655 117.555,93.655 118.325,94.425 C37.2@119.05,94.425 v1(120.325,94.425) ; v1(118.95,87.45) 119.6,87.45 120.425,86.625 R50.2@120.5,86.625 120.625,86.75 121.675,86.75 Q8.1@122.05,87.125 ; v1(120.475,92.25) R48.2@120.475,91.675 120.625,91.825 121.675,91.825 Q7.1@122.05,92.2
  Signal Layer 2 w0.2: v1(111.55,94.4) 111.55,102.125 112.15,102.725 TP16.1@112.15,104.75
  Bottom Layer w0.2: SB104.2@122.5,101.925 v1(123.7,101.925)
  other v1: 123.704,102.468
3V3: C1.2 C109.2 CN2.28 CN9.50 CN14.34 CN15.34 JP5.1 JP17.3 JP23.1 R1.2 R3.2 R4.1 R5.2 R6.1 R78.1 R100.2 R130.2 R131.2 R132.2 R133.2 R248.2 SB4.2 SB10.1 SB56.1 SB125.1 SB128.1 TP28.1 U1.2 U31.1 U31.3 U42.2 | length 46.7
  Top Layer w0.1: R100.2@19.775,35.8 v1(19.775,36.425)
  Top Layer w0.12: R248.2@11.958,47.709 11.963,47.704 v1(12.687,47.704)
  Top Layer w0.2: C1.2@117.35,159.7 117.45,159.6 U1.2@118.8,159.6
  Top Layer w0.25: R130.2@7.25,9.1 v1(7.25,10.823) ; v1(8.951,10.895) 8.951,9.299 R131.2@9.15,9.1 ; R132.2@11.15,9.1 v1(11.15,10.69) ; v1(13.072,10.677) 13.072,9.178 R133.2@13.15,9.1 ; v1(30.525,159.875) R4.1@31.525,159.875 ; CN9.50@46.043,114.525 v1(47.955,114.525) ; R1.2@53.7,167.8 54.005,167.8 56.412,165.393 v1(56.412,160.827) ; CN14.34@56.025,84.17 57.85,84.17 58.173,84.493 v1(58.173,84.859) ; R5.2@69.4,158.7 69.424,158.7 70.275,159.551 v1(70.275,159.575) ; R6.1@100.05,158.7 100.05,157.65 101.4,156.3 v1(101.4,155.275) ; v1(104.641,83.214) CN15.34@104.641,84.17 ; R3.2@112.775,162.85 v1(112.775,163.55) ; v1(116.525,159.7) C1.2@117.35,159.7 ; v1(134.825,56.075) R78.1@135.65,56.075
  Signal Layer 2 w0.25: CN2.28@70.202,165.1 70.202,159.648 v1(70.275,159.575)
  Bottom Layer w0.25: v1(15.975,126.675) SB56.1@17.15,126.675 ; v1(30.525,159.875) SB10.1@31.725,159.875 ; v1(30.529,149.525) 30.529,149.879 30.65,150 U42.2@31.4,150 ; v1(95.025,37.625) 95.5,38.1 99,38.1 ; SB128.1@117.6,30.3 v1(118.9,30.3)
  other v1: 123.175,22.35
3V3_RS232: C133.1 C153.1 SB56.2 U43.22 U43.26 U45.8 | length 32.2
  Bottom Layer w0.2: SB56.2@18.25,126.675 18.375,126.675 18.7,127 C133.1@18.7,128.075 19.086,128.461 U43.26@20.976,128.461 ; SB56.2@18.362,126.662 v1(19.164,125.861) ; U43.22@20.976,125.861 v1(19.164,125.861) ; U45.8@26.2,116.625 26.2,116.025 25.75,115.575 C153.1@25.05,115.575 25.05,114.075 24.88,113.905 18.92,113.905 14.75,118.075 14.75,121.447 v1(19.164,125.861)
3V3_STLK: C56.2 C58.1 C75.1 C81.2 C82.1 C95.2 C105.2 C161.1 C162.1 C163.1 C164.1 C165.1 C166.1 C167.1 C168.1 C169.1 C170.1 C172.1 C173.1 C174.1 C175.1 C176.1 C178.1 C179.1 CN28.1 LD4.4 R92.2 U23.5 U26.C1 U26.C5 U26.C6 U26.C7 U26.C8 U26.C9 U26.F3 U26.G3 U26.G13 U26.H13 U26.J12 U26.J13 U26.K4 U26.N8 U26.N9 U26.N10 U26.P1 U26.R1 U27.1 U30.1 X3.4 | length 36.8
  Top Layer w0.1: v1(23.575,39.775) 24.475,39.775 R92.2@24.7,39.55 ; X3.4@27.4,40.95 C75.1@28.575,40.95 v1(29.2,40.95)
  Top Layer w0.2: v1(21.875,36) U26.R1@22.2,35.675 ; v1(22.525,36) U26.P1@22.85,35.675 ; v1(23.175,29.5) U26.N10@23.5,29.825 ; v1(23.175,30.15) U26.N9@23.5,30.475 ; v1(23.175,30.8) U26.N8@23.5,31.125 ; v1(25.125,34.05) U26.K4@25.45,33.725 ; v1(25.775,27.55) U26.J13@26.1,27.875 ; v1(25.775,28.2) U26.J12@26.1,28.525 ; U26.H13@26.75,27.875 v1(27.075,27.55) ; U26.G13@27.4,27.875 v1(27.725,27.55) ; U26.G3@27.4,34.375 v1(27.725,34.7) ; U26.F3@28.05,34.375 v1(28.375,34.7) ; U26.C9@30,30.475 v1(30.325,30.15) ; U26.C8@30,31.125 v1(30.325,31.45) ; U26.C7@30,31.775 v1(30.325,32.1) ; U26.C6@30,32.425 v1(30.325,32.75) ; U26.C5@30,33.075 v1(30.325,33.4) ; U26.C1@30,35.675 v1(30.325,36)
  Top Layer w0.25: v1(4.65,3.409) LD4.4@4.65,5.3 ; v1(30.325,36) 30.325,36.794 31.044,37.513 C82.1@32.101,37.513 ; C82.1@32.133,37.444 32.176,37.402 33.098,37.402 C81.2@33.25,37.25 ; U27.1@42.025,32 C95.2@42.025,30.975 v1(44.525,30.975) ; U30.1@42.048,27.799 42.025,27.776 C105.2@42.025,26.775 v1(44.625,26.775)
  Bottom Layer w0.1: v1(21.875,36) 21.875,35.5 22.05,35.325 C165.1@22.4,35.325 ; C161.1@22.4,36.725 22.525,36.6 v1(22.525,36) ; C174.1@22.55,29.3 22.75,29.5 v1(23.175,29.5) ; C172.1@22.55,30.15 v1(23.175,30.15) ; C169.1@23.05,31.375 23.175,31.25 v1(23.175,30.8) ; C175.1@25.075,28.2 v1(25.775,28.2) ; C167.1@25.125,33.35 v1(25.125,34.05) ; C179.1@25.775,26.825 v1(25.775,27.55) ; C176.1@26.425,27.65 26.525,27.55 v1(27.075,27.55) ; C164.1@27.1,34.575 27.225,34.7 v1(27.725,34.7) ; C178.1@27.725,26.85 v1(27.725,27.55) ; v1(28.375,34.7) 28.925,34.7 C163.1@29.05,34.575 ; v1(30.325,30.15) 30.325,29.675 C173.1@30.45,29.55 ; v1(30.325,31.45) 30.325,30.925 C170.1@30.45,30.8 ; v1(30.325,32.1) C168.1@31.125,32.1 ; v1(30.325,33.4) C166.1@31.125,33.4 ; v1(30.325,36) C162.1@31.05,36
  other v1: 44.528,55.625 45.15,56.25
5V: C33.2 C46.2 C48.2 CN2.25 CN7.6 CN7.15 CN10.50 JP25.2 JP25.4 JP25.6 JP25.8 JP25.10 R64.1 R65.1 R67.1 R106.1 SB5.1 SB118.1 SB127.1 U10.3 U18.6 U19.6 | length 273.9
  Top Layer w0.25: v1(7.85,68.7) R67.1@8.7,68.7
  Top Layer w0.5: v1(14.2,72.4) R64.1@15,72.4 ; v1(16.875,31.875) R106.1@16.875,32.6 ; v1(42.925,74.425) 42.375,73.875 42.375,72.25 43.1,71.525 R65.1@43.1,71.3 ; CN10.50@114.623,114.525 v1(118.07,114.525) ; v1(120.275,52.2) 120.275,53 SB5.1@120.45,53.175 ; U10.3@127.25,99.95 C33.2@127.25,101.925 128.425,101.925 129.375,100.975 v1(131.875,100.975)
  Signal Layer 2 w0.5: v1(84.075,1.625) 84.075,12.325 87.9,16.15 87.9,41.6 85.2,44.3 v1(85.2,47.634)
  Signal Layer 4 w0.5: 7.225,72.4 v1(14.2,72.4) 14.725,72.925 v1(14.725,75.475) 14.725,76.575 v1(14.7,76.6) ; 7.9,55.325 8.7,54.525 10.325,54.525 12.555,56.755 20.596,56.755 20.807,56.966 34.041,56.966 37.105,60.03 37.105,72.73 39.675,75.3 v1(43.025,75.3) ; v1(118.07,114.525) 118.07,115.245 118.625,115.8 120.134,115.8 120.329,115.995 121.805,115.995 122.675,115.125 127.034,115.125 127.134,115.225 128.15,115.225 130.825,112.55 135.975,112.55 137.675,114.25 149.925,114.25 ; v1(118.9,31.9) 122.125,31.9 127.05,36.825 153.1,36.825 ; v1(120.275,52.2) 130.675,52.2 134.975,47.9 142.475,47.9 143.9,49.325 153.35,49.325 ; v1(131.875,100.975) 132.125,101.225 153.15,101.225
  Signal Layer 4 w0.58: 2.8,32.25 3.175,31.875 v1(16.875,31.875)
  Bottom Layer w0.5: v1(85.2,47.634) 85.22,47.654 85.22,48.7 SB118.1@85.2,48.7 ; SB127.1@117.6,31.9 v1(118.9,31.9)
  other v1: 84.075,2.375
5V_DC: CN9.49 D5.1 JP25.7 | length 32.8
  Top Layer w0.5: v1(32.65,60) v1(33.403,60) D5.1@34.33,60 ; v1(34.855,114.525) 37.482,114.525 37.776,114.231 39.382,114.231 39.676,114.525 CN9.49@40.943,114.525
  Bottom Layer w2: JP25.7@9.409,63.7 17.97,63.7 21.67,60 v1(32.65,60)
  other v1: 35.562,114.519
5V_EXT: C60.1 C64.1 C188.2 D7.1 F1.2 JP25.3 U49.5 U51.1 | length 34.2
  Top Layer w0.25: v1(17.398,46.203) 16.448,46.203 C60.1@15.816,46.835 ; v1(17.399,46.978) 15.959,46.978 C60.1@15.816,46.835 ; v1(17.399,47.728) 16.474,47.728 C60.1@15.699,46.953 C60.1@15.816,46.835
  Top Layer w0.5: v1(32.65,56) v1(33.403,56) D7.1@34.33,56
  Bottom Layer w1: JP25.3@9.409,58.62 13.223,58.62 17.937,53.907 24.964,53.907 27.057,56 v1(33.403,56)
5V_EXT_UNFILT: C182.2 C183.2 C184.2 CN25.1 R247.1 U50.1
5V_FDCAN: C59.1 SB5.2 U22.3 | length 5.2
  Top Layer w0.25: SB5.2@121.55,53.175 121.55,52.1 121.825,51.825 C59.1@123.55,51.825 123.835,51.54 U22.3@125.475,51.54
5V_SC: C159.1 C160.2 SB118.2 U21.6 | length 6.1
  Top Layer w0.3: v1(83.155,52.289) U21.6@83.155,53.931
  Bottom Layer w0.3: v1(83.155,52.289) 83.542,52.289 84.05,51.781 C159.1@84.05,51.6 83.947,51.497 83.947,50.447 C160.2@83.8,50.3 83.8,48.937 84.037,48.7 SB118.2@84.1,48.7
5V_STLK: C61.1 JP25.1 U20.1 | length 20.4
  Top Layer w0.4: v1(24.709,51.975) C61.1@25.95,51.975 U20.1@25.95,53.375
  Bottom Layer w1: JP25.1@9.387,56.084 13.143,56.084 16.939,52.288 24.395,52.288 v1(24.709,51.975) v1(25.425,51.975)
5V_UCPD: D6.1 JP6.1 JP7.1 JP8.1 JP25.5 | length 1.9
  Top Layer w0.5: v1(33.276,58.006) 34.324,58.006 D6.1@34.33,58
  Top Layer w0.8: v1@32.475,58.006 v1(33.276,58.006)
  other v1: 32.475,58
5V_UNPROTECT: C185.2 C186.2 C187.2 F1.1 R247.2 R249.2 U49.3 U49.4 | length 1
  Top Layer w0.12: R249.2@2.823,47.831 2.823,47.736 3.018,47.541 3.113,47.541 3.493,47.162 C187.2@3.493,47.152
5V_USB_CHGR: C54.1 C107.2 CN26.1 D4.1 JP25.9 R80.2 R82.2 U20.5 U34.1 | length 8.7
  Top Layer w0.25: R82.2@27.85,50.5 v1(28.75,50.5)
  Top Layer w0.5: CN26.1@4.15,22.375 4.9,22.375 6.05,23.525 U34.1@6.175,23.525 6.21,23.56 7.173,23.56 7.313,23.7 C107.2@7.45,23.7 v1(8.125,23.7) v1(8.125,24.475) v1(8.125,25.275) ; v1(32.65,62) v1(33.403,62) D4.1@34.33,62
  other v1: 21.9,55.575 21.982,56.371
A0: R205.2 U12.A3 | length 28
  Top Layer w0.1: v1(73.904,90.446) U12.A3@75.4,90.446
  Bottom Layer w0.1: R205.2@60.375,94.325 60.976,94.925 64.525,94.925 64.65,94.8 64.65,94.55 64.5,94.4 61.125,94.4 61,94.275 61,94.05 61.108,93.942 64.577,93.942 65.402,94.767 70.358,94.767 70.8,94.325 73.325,94.325 74.725,92.925 74.725,91.267 v1(73.904,90.446)
A1: R208.2 U12.A4 | length 27.6
  Top Layer w0.1: v1(73.904,91.196) U12.A4@75.4,91.196
  Bottom Layer w0.1: R208.2@60.375,93.075 60.825,93.525 64.75,93.525 65.575,94.35 69.975,94.35 70.1,94.225 70.1,93.975 70,93.875 65.65,93.875 65.55,93.775 65.55,93.45 65.65,93.35 73.45,93.35 74.325,92.475 74.325,91.617 v1(73.904,91.196)
A2: R214.2 U12.A5 | length 27
  Top Layer w0.1: v1(73.904,91.946) U12.A5@75.4,91.946
  Bottom Layer w0.1: R214.2@60.375,91.8 61.025,91.8 61.423,92.198 61.613,92.198 61.715,92.3 67.475,92.3 67.6,92.175 67.6,92.025 67.475,91.9 62.175,91.9 62.075,91.8 62.075,91.575 62.158,91.492 67.602,91.492 68.056,91.946 v1(73.904,91.946)
A3: R218.2 U12.B3 | length 27
  Top Layer w0.1: v1(74.904,90.071) 75.775,90.071 U12.B3@76.15,90.446
  Bottom Layer w0.1: R218.2@60.375,90.525 60.926,91.075 67.775,91.075 68.125,91.425 73,91.425 73.125,91.3 73.125,91.075 73.05,91 68.275,91 68.2,90.925 68.2,90.625 68.297,90.528 71.172,90.528 71.629,90.071 v1(74.904,90.071)
A4: R223.2 U12.B4 | length 28.7
  Top Layer w0.1: v1(74.904,90.821) 75.775,90.821 U12.B4@76.15,91.196
  Bottom Layer w0.1: R223.2@60.375,89.25 61.8,89.25 62.244,89.694 68.731,89.694 68.85,89.575 68.85,89.375 68.75,89.275 66.15,89.275 66.025,89.15 66.025,88.95 66.108,88.867 68.902,88.867 69.31,89.275 74.85,89.275 75.925,90.35 75.925,92.4 75.825,92.5 75.6,92.5 75.5,92.4 75.5,90.9 75.421,90.821 v1(74.904,90.821)
A5: R227.2 U12.C3 | length 27.2
  Top Layer w0.1: v1(76.55,90.096) U12.C3@76.9,90.446
  Bottom Layer w0.1: R227.2@60.375,87.975 60.851,88.45 69.075,88.45 69.475,88.85 74.05,88.85 74.175,88.725 74.175,88.55 74.05,88.425 69.875,88.425 69.8,88.35 69.8,88.1 69.875,88.025 74.479,88.025 v1(76.55,90.096)
A6: R225.2 U12.C4 | length 27.2
  Top Layer w0.1: v1(76.55,91.546) U12.C4@76.9,91.196
  Bottom Layer w0.1: v1(76.55,91.546) 77.446,90.65 79.625,90.65 79.95,90.325 79.95,89.75 81.175,88.525 84.925,88.525 85.858,89.458 88.142,89.458 88.275,89.325 88.275,89.125 88.175,89.025 86.05,89.025 85.9,88.875 85.9,88.625 86,88.525 89.975,88.525 90.5,88 R225.2@95.625,88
